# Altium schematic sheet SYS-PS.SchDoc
size A3
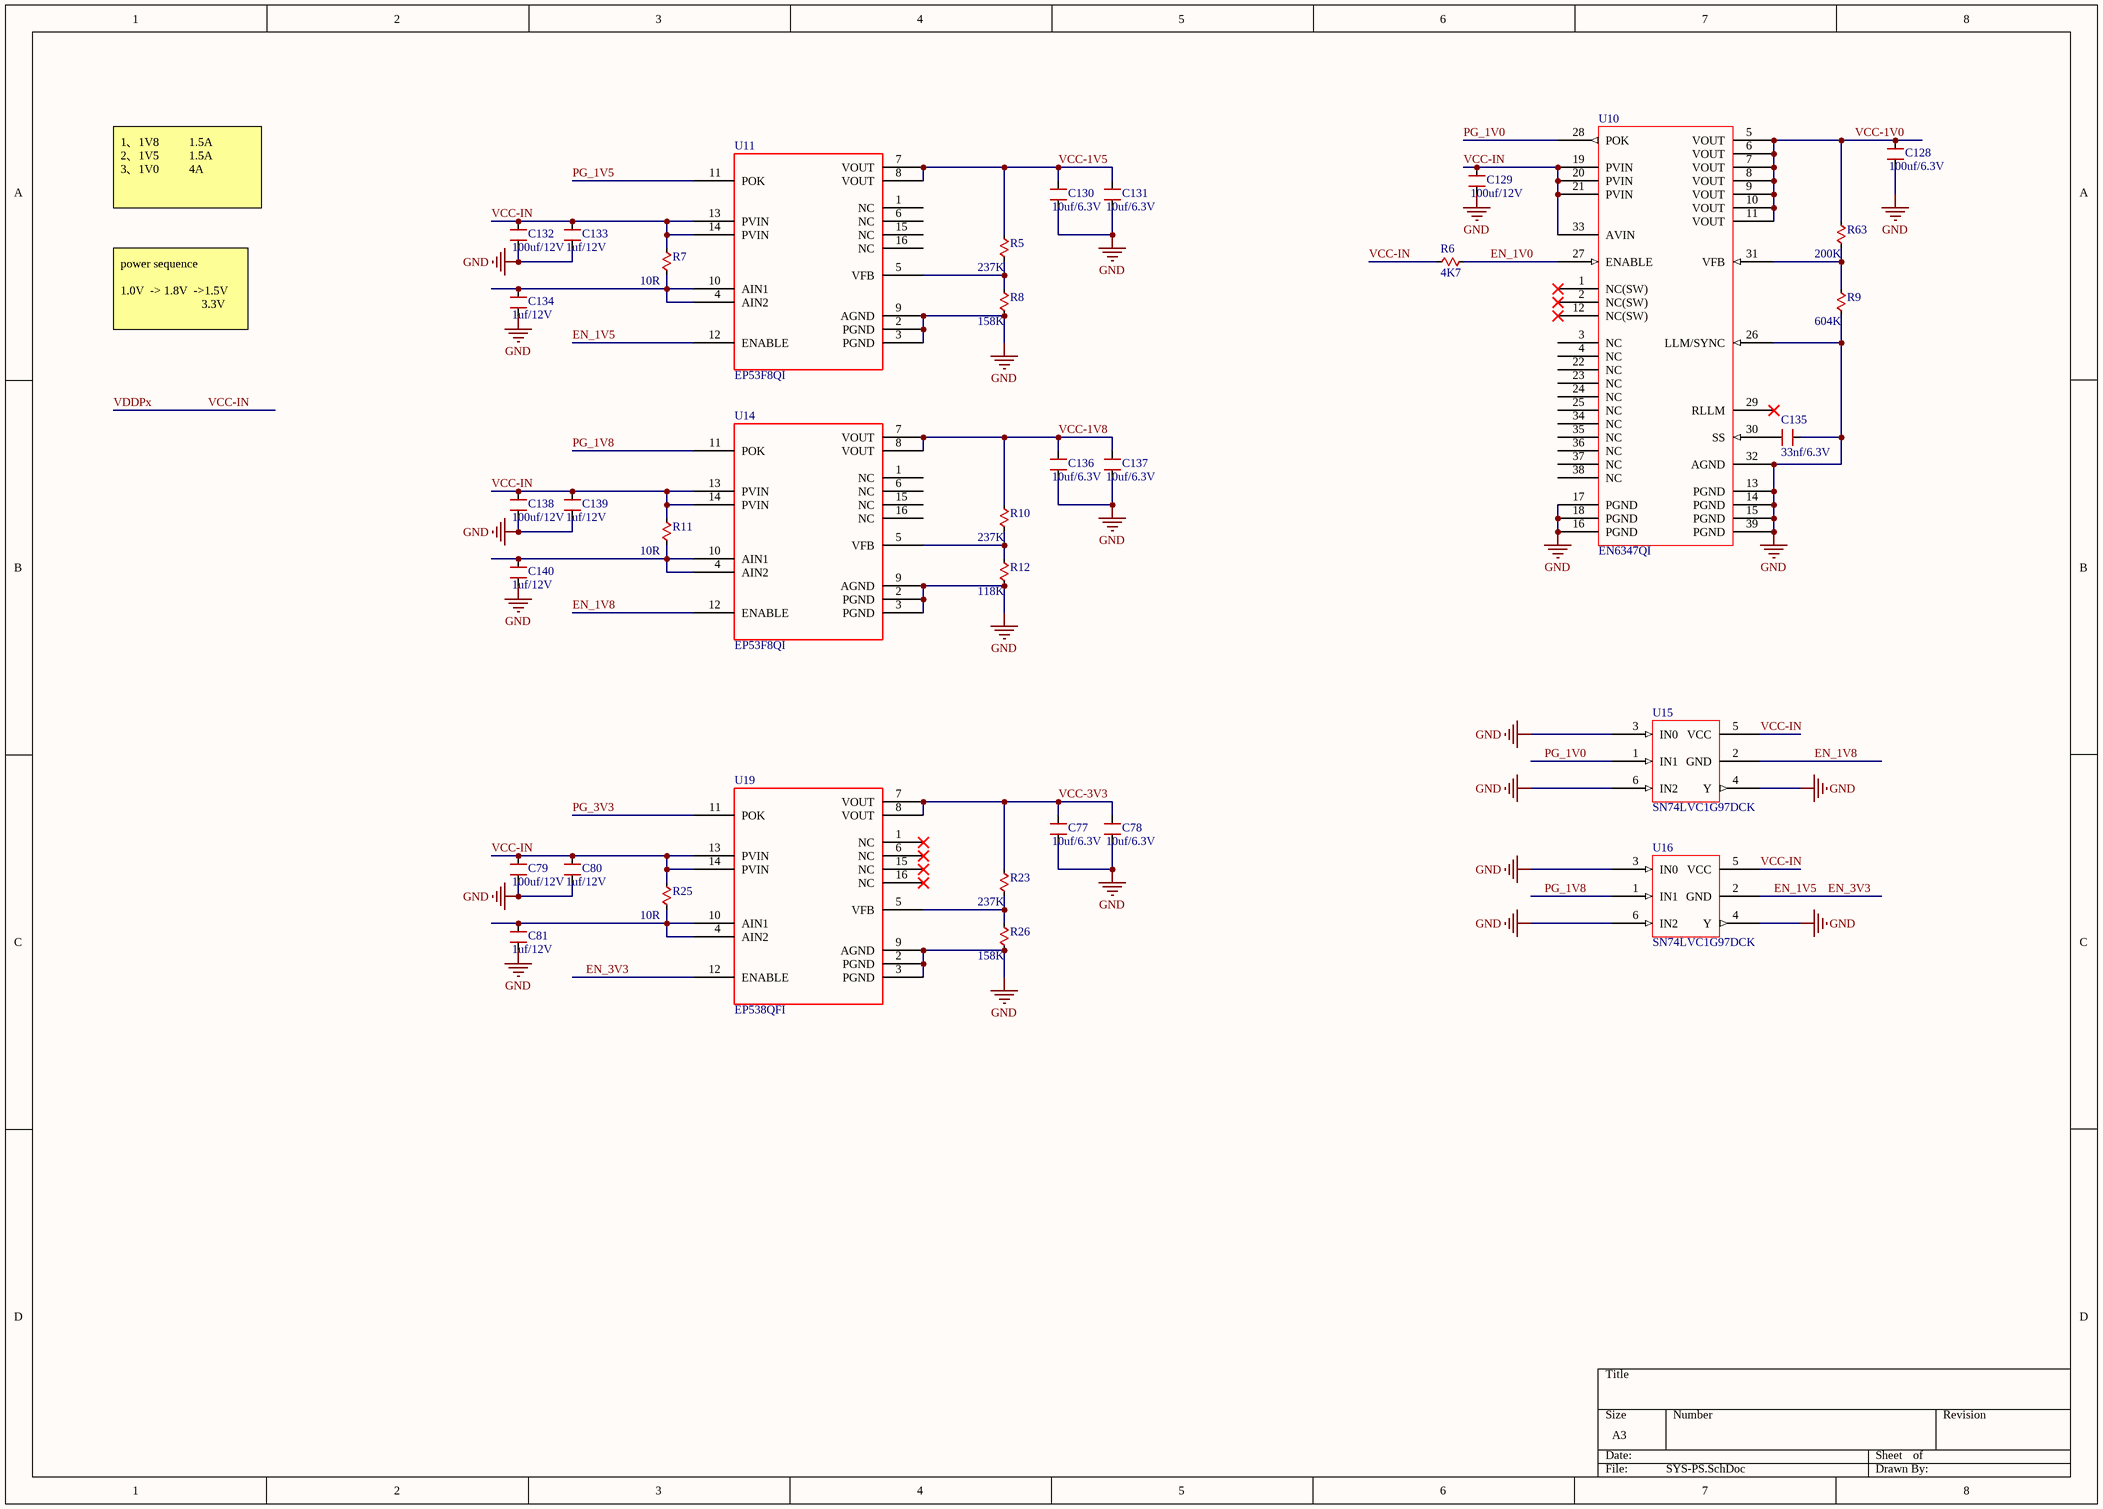
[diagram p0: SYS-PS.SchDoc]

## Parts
C77  10uf/6.3V  [0603]
C78  10uf/6.3V  [0603]
C79  100uf/12V  [0805]
C80  1uf/12V  [0402]
C81  1uf/12V  [0402]
C128  100uf/6.3V  [0805]
C129  100uf/12V  [0805]
C130  10uf/6.3V  [0603]
C131  10uf/6.3V  [0603]
C132  100uf/12V  [0805]
C133  1uf/12V  [0402]
C134  1uf/12V  [0402]
C135  33nf/6.3V  [0402]
C136  10uf/6.3V  [0603]
C137  10uf/6.3V  [0603]
C138  100uf/12V  [0805]
C139  1uf/12V  [0402]
C140  1uf/12V  [0402]
R5  237K  [0402]
R6  4K7  [0402]
R7  10R  [0402]
R8  158K  [0402]
R9  604K  [0402]
R10  237K  [0402]
R11  10R  [0402]
R12  118K  [0402]
R23  237K  [0402]
R25  10R  [0402]
R26  158K  [0402]
R63  200K  [0402]
U10  EN6347QI  [EN6347-QFN]
U11  EP53F8QI  [QFN16]
U14  EP53F8QI  [QFN16]
U15  SN74LVC1G97DCK  [SC70-DCK]
U16  SN74LVC1G97DCK  [SC70-DCK]
U19  EP538QFI  [QFN16]

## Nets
GND: C77.2 C78.2 C79.2 C80.2 C81.2 C128.2 C129.2 C130.2 C131.2 C132.2 C133.2 C134.2 C135.2 C136.2 C137.2 C138.2 C139.2 C140.2 R8.2 R9.2 R12.2 R26.2 U10.13(PGND) U10.14(PGND) U10.15(PGND) U10.16(PGND) U10.17(PGND) U10.18(PGND) U10.26(LLM/SYNC) U10.32(AGND) U10.39(PGND) U11.2(PGND) U11.3(PGND) U11.9(AGND) U14.2(PGND) U14.3(PGND) U14.9(AGND) U15.3(IN0) U15.4(Y) U15.6(IN2) U16.3(IN0) U16.4(Y) U16.6(IN2) U19.2(PGND) U19.3(PGND) U19.9(AGND)
EN_1V0: R6.1 U10.27(ENABLE)
EN_1V5: U11.12(ENABLE) U16.2(GND) U19.12(ENABLE)  [also labelled EN_3V3]
EN_1V8: U14.12(ENABLE) U15.2(GND)
PG_1V0: U10.28(POK) U15.1(IN1)
PG_1V5: U11.11(POK)
PG_1V8: U14.11(POK) U16.1(IN1)
PG_3V3: U19.11(POK)
VCC-1V0: C128.1 R63.1 U10.5(VOUT) U10.6(VOUT) U10.7(VOUT) U10.8(VOUT) U10.9(VOUT) U10.10(VOUT) U10.11(VOUT)
VCC-1V5: C130.1 C131.1 R5.1 U11.7(VOUT) U11.8(VOUT)
VCC-1V8: C136.1 C137.1 R10.1 U14.7(VOUT) U14.8(VOUT)
VCC-3V3: C77.1 C78.1 R23.1 U19.7(VOUT) U19.8(VOUT)
VCC-IN: C79.1 C80.1 C129.1 C132.1 C133.1 C138.1 C139.1 R6.2 R7.1 R11.1 R25.1 U10.19(PVIN) U10.20(PVIN) U10.21(PVIN) U10.33(AVIN) U11.13(PVIN) U11.14(PVIN) U14.13(PVIN) U14.14(PVIN) U15.5(VCC) U16.5(VCC) U19.13(PVIN) U19.14(PVIN)  [also labelled VDDPx]
NetC81_1: C81.1 R25.2 U19.4(AIN2) U19.10(AIN1)
NetC134_1: C134.1 R7.2 U11.4(AIN2) U11.10(AIN1)
NetC135_1: C135.1 U10.30(SS)
NetC140_1: C140.1 R11.2 U14.4(AIN2) U14.10(AIN1)
NetR5_2: R5.2 R8.1 U11.5(VFB)
NetR9_1: R9.1 R63.2 U10.31(VFB)
NetR10_2: R10.2 R12.1 U14.5(VFB)
NetR23_2: R23.2 R26.1 U19.5(VFB)

Not connected (* = marked no-connect by the designer): U10 1(NC(SW))* 2(NC(SW))* 3(NC) 4(NC) 12(NC(SW))* 22(NC) 23(NC) 24(NC) 25(NC) 29(RLLM)* 34(NC) 35(NC) 36(NC) 37(NC) 38(NC); U11 1(NC) 6(NC) 15(NC) 16(NC); U14 1(NC) 6(NC) 15(NC) 16(NC); U19 1(NC)* 6(NC)* 15(NC)* 16(NC)*

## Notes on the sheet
- 1、1V8          1.5A
  2、1V5          1.5A
  3、1V0          4A
- power sequence
  1.0V  -> 1.8V  ->1.5V
  3.3V

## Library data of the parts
C77-C81 C128-C140 = CAPACITOR: Generic Capacitor
R5-R12 R23 R25 R26 R63 = RESISTOR: Generic Resistor; Value: 10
